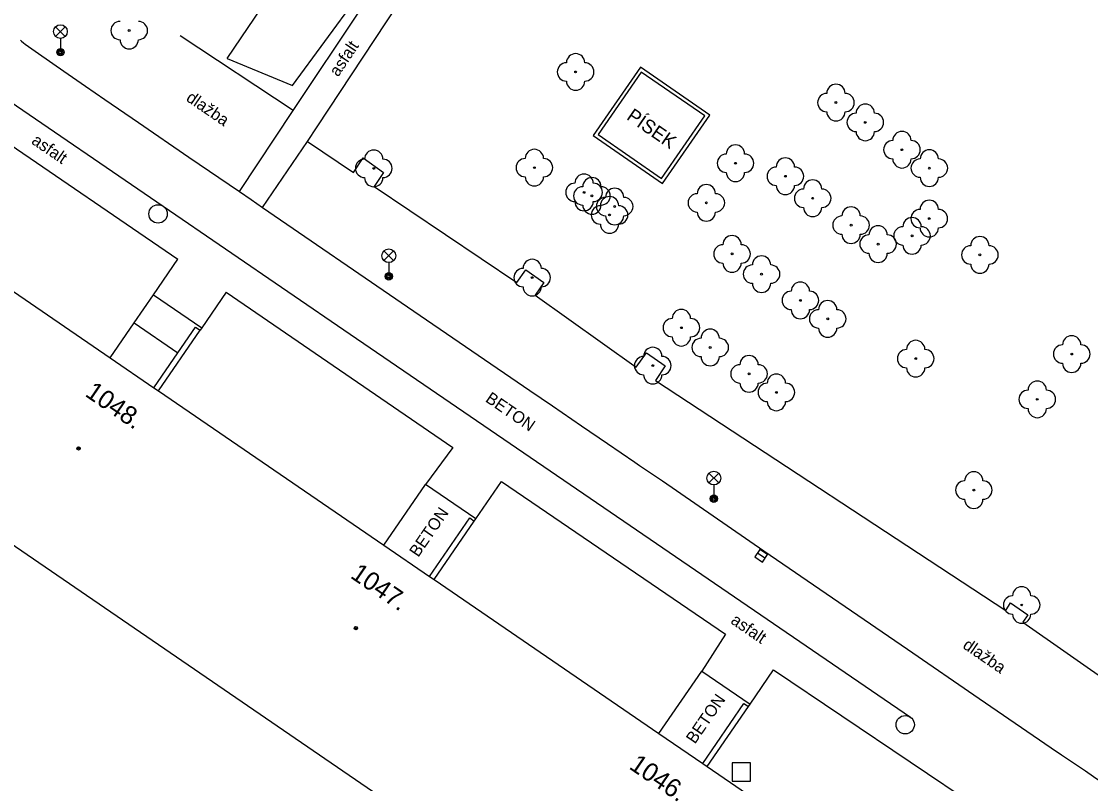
# Model space of a CAD drawing. Extents: x -539515 to -538098, y -1182060 to -1180157.
# Drawn here: x -538687.3 to -538629, y -1181340.3 to -1181298.7 of the extents above; entities that cross this region are included whole.
import ezdxf

# ---------------------------------------------------------------- set-up
doc = ezdxf.new("R2010")
doc.units = 0
for name, color, linetype in [('Vrstva 1', 7, 'Continuous'), ('Vrstva 13', 7, 'Continuous'), ('Vrstva 21', 7, 'Continuous'), ('Vrstva 22', 7, 'Continuous'), ('Vrstva 26', 7, 'Continuous'), ('Vrstva 27', 7, 'Continuous'), ('Vrstva 33', 7, 'Continuous'), ('Vrstva 39', 7, 'Continuous'), ('Vrstva 40', 7, 'Continuous'), ('Vrstva 41', 7, 'Continuous'), ('Vrstva 47', 7, 'Continuous'), ('Vrstva 68', 7, 'Continuous'), ('Vrstva 88', 7, 'Continuous')]:
    doc.layers.add(name, color=color, linetype=linetype)

msp = doc.modelspace()

# ---------------------------------------------------------------- linework, layer by layer
at = {"layer": 'Vrstva 1'}
for p, q in [((-538724.84, -1181301.89), (-538635.14, -1181363.33)), ((-538682.46, -1181317.088), (-538681.15, -1181315.18)), ((-538681.15, -1181315.18), (-538678.77, -1181316.81))]:
    msp.add_line(p, q, dxfattribs=at)
for points in [[(-538694.6, -1181308.773), (-538682.46, -1181317.088)], [(-538682.46, -1181317.088), (-538680.078, -1181318.719)], [(-538680.078, -1181318.719), (-538679.831, -1181318.889)], [(-538679.831, -1181318.889), (-538667.542, -1181327.306)], [(-538667.542, -1181327.306), (-538665.045, -1181329.015)], [(-538665.045, -1181329.015), (-538664.798, -1181329.185)], [(-538664.798, -1181329.185), (-538652.533, -1181337.586)], [(-538652.533, -1181337.586), (-538650.149, -1181339.218)], [(-538650.149, -1181339.218), (-538649.902, -1181339.388)], [(-538649.902, -1181339.388), (-538637.736, -1181347.722)]]:
    msp.add_lwpolyline(points, dxfattribs=at)
at = {"layer": 'Vrstva 13'}
for p, q in [((-538672.49, -1181303.59), (-538678.657, -1181299.511)), ((-538690.92, -1181303.4), (-538678.77, -1181311.7)), ((-538671.707, -1181305.275), (-538669.196, -1181306.972)), ((-538668.06, -1181307.74), (-538660.29, -1181312.97)), ((-538658.81, -1181312.97), (-538659.291, -1181313.663)), ((-538680.104, -1181313.648), (-538677.475, -1181315.449)), ((-538676.14, -1181313.5), (-538663.78, -1181321.97)), ((-538659.291, -1181313.663), (-538653.78, -1181317.59)), ((-538652.73, -1181318.33), (-538633.61, -1181330.87)), ((-538663.78, -1181321.97), (-538665.27, -1181323.99)), ((-538661.13, -1181323.83), (-538648.91, -1181332.17)), ((-538667.542, -1181327.306), (-538665.27, -1181323.99)), ((-538662.527, -1181325.869), (-538665.27, -1181323.99)), ((-538632.69, -1181331.5), (-538606.03, -1181350.16)), ((-538648.91, -1181332.17), (-538650.2, -1181334.18)), ((-538652.533, -1181337.586), (-538650.2, -1181334.18)), ((-538650.2, -1181334.18), (-538647.568, -1181335.981)), ((-538646.28, -1181334.1), (-538634.05, -1181342.34))]:
    msp.add_line(p, q, dxfattribs=at)
for points in [[(-538671.17, -1181304.48), (-538663.02, -1181292.1)], [(-538672.49, -1181303.59), (-538665.1, -1181292.51)], [(-538675.42, -1181308.02), (-538672.49, -1181303.59)], [(-538674.15, -1181308.89), (-538671.707, -1181305.275), (-538671.17, -1181304.48)], [(-538669.196, -1181306.972), (-538668.66, -1181306.18), (-538667.56, -1181306.97), (-538668.06, -1181307.74)], [(-538681.15, -1181315.18), (-538680.104, -1181313.648), (-538678.77, -1181311.7)], [(-538660.29, -1181312.97), (-538659.79, -1181312.29), (-538658.81, -1181312.97)], [(-538676.14, -1181313.5), (-538677.475, -1181315.449), (-538677.56, -1181315.573)], [(-538653.78, -1181317.59), (-538653.21, -1181316.81), (-538652.19, -1181317.53), (-538652.73, -1181318.33)], [(-538662.611, -1181325.992), (-538662.527, -1181325.869), (-538661.13, -1181323.83)], [(-538633.61, -1181330.87), (-538633.36, -1181330.45), (-538632.41, -1181331.11), (-538632.69, -1181331.5)], [(-538647.653, -1181336.105), (-538647.568, -1181335.981), (-538646.28, -1181334.1)]]:
    msp.add_lwpolyline(points, dxfattribs=at)
at = {"layer": 'Vrstva 21'}
for p, q in [((-538676.09, -1181300.75), (-538670.086, -1181291.901)), ((-538672.53, -1181302.22), (-538666.46, -1181293.99)), ((-538676.09, -1181300.75), (-538672.53, -1181302.22))]:
    msp.add_line(p, q, dxfattribs=at)
at = {"layer": 'Vrstva 22'}
for centre in [(-538681.43, -1181299.23), (-538657.08, -1181301.49), (-538642.88, -1181303.16), (-538641.28, -1181304.24), (-538639.28, -1181305.73), (-538668.09, -1181306.75), (-538659.33, -1181306.71), (-538648.36, -1181306.47), (-538637.787, -1181306.736), (-538645.64, -1181307.18), (-538656.62, -1181308.06), (-538656.19, -1181308.25), (-538649.95, -1181308.63), (-538644.15, -1181308.38), (-538655.23, -1181309.29), (-538654.95, -1181308.83), (-538642.055, -1181309.847), (-538637.79, -1181309.49), (-538638.73, -1181310.43), (-538640.58, -1181310.88), (-538648.548, -1181311.416), (-538635.03, -1181311.47), (-538659.45, -1181312.71), (-538646.94, -1181312.52), (-538644.822, -1181313.952), (-538643.33, -1181314.96), (-538651.311, -1181315.441), (-538649.74, -1181316.52), (-538630.02, -1181316.88), (-538638.53, -1181317.13), (-538652.87, -1181317.51), (-538647.62, -1181317.959), (-538646.13, -1181318.97), (-538631.9, -1181319.35), (-538635.36, -1181324.3), (-538632.75, -1181330.57)]:
    msp.add_circle(centre, 0.05, dxfattribs=at)
for centre, start, end in [((-538681.93, -1181299.23), 90, 270), ((-538680.93, -1181299.23), 270, 90), ((-538681.43, -1181299.73), 180, 0), ((-538657.08, -1181300.99), 0, 180), ((-538657.58, -1181301.49), 90, 270), ((-538656.58, -1181301.49), 270, 90), ((-538657.08, -1181301.99), 180, 0), ((-538642.88, -1181302.66), 0, 180), ((-538643.38, -1181303.16), 90, 270), ((-538642.38, -1181303.16), 270, 90), ((-538641.28, -1181303.74), 0, 180), ((-538642.88, -1181303.66), 180, 0), ((-538641.78, -1181304.24), 90, 270), ((-538640.78, -1181304.24), 270, 90), ((-538641.28, -1181304.74), 180, 0), ((-538639.28, -1181305.23), 0, 180), ((-538668.09, -1181306.25), 0, 180), ((-538659.33, -1181306.21), 0, 180), ((-538648.36, -1181305.97), 0, 180), ((-538639.78, -1181305.73), 90, 270), ((-538638.78, -1181305.73), 270, 90), ((-538637.787, -1181306.236), 0, 180), ((-538668.59, -1181306.75), 90, 270), ((-538667.59, -1181306.75), 270, 90), ((-538659.83, -1181306.71), 90, 270), ((-538658.83, -1181306.71), 270, 90), ((-538648.86, -1181306.47), 90, 270), ((-538647.86, -1181306.47), 270, 90), ((-538645.64, -1181306.68), 0, 180), ((-538639.28, -1181306.23), 180, 0), ((-538638.287, -1181306.736), 90, 270), ((-538637.287, -1181306.736), 270, 90), ((-538646.14, -1181307.18), 90, 270), ((-538645.14, -1181307.18), 270, 90), ((-538668.09, -1181307.25), 180, 0), ((-538659.33, -1181307.21), 180, 0), ((-538656.62, -1181307.56), 0, 180), ((-538656.19, -1181307.75), 0, 180), ((-538648.36, -1181306.97), 180, 0), ((-538644.15, -1181307.88), 0, 180), ((-538637.787, -1181307.236), 180, 0), ((-538657.12, -1181308.06), 90, 270), ((-538656.69, -1181308.25), 90, 270), ((-538656.12, -1181308.06), 270, 90), ((-538655.69, -1181308.25), 270, 90), ((-538654.95, -1181308.33), 0, 180), ((-538649.95, -1181308.13), 0, 180), ((-538645.64, -1181307.68), 180, 0), ((-538644.65, -1181308.38), 90, 270), ((-538643.65, -1181308.38), 270, 90), ((-538656.62, -1181308.56), 180, 0), ((-538655.45, -1181308.83), 90, 270), ((-538655.23, -1181308.79), 0, 180), ((-538654.45, -1181308.83), 270, 90), ((-538650.45, -1181308.63), 90, 270), ((-538649.45, -1181308.63), 270, 90), ((-538637.79, -1181308.99), 0, 180), ((-538656.19, -1181308.75), 180, 0), ((-538655.73, -1181309.29), 90, 270), ((-538654.73, -1181309.29), 270, 90), ((-538649.95, -1181309.13), 180, 0), ((-538644.15, -1181308.88), 180, 0), ((-538642.055, -1181309.347), 0, 180), ((-538638.29, -1181309.49), 90, 270), ((-538637.29, -1181309.49), 270, 90), ((-538655.23, -1181309.79), 180, 0), ((-538654.95, -1181309.33), 180, 0), ((-538642.555, -1181309.847), 90, 270), ((-538641.555, -1181309.847), 270, 90), ((-538638.73, -1181309.93), 0, 180), ((-538648.548, -1181310.916), 0, 180), ((-538642.055, -1181310.347), 180, 0), ((-538641.08, -1181310.88), 90, 270), ((-538640.58, -1181310.38), 0, 180), ((-538640.08, -1181310.88), 270, 90), ((-538639.23, -1181310.43), 90, 270), ((-538637.79, -1181309.99), 180, 0), ((-538638.23, -1181310.43), 270, 90), ((-538649.048, -1181311.416), 90, 270), ((-538648.048, -1181311.416), 270, 90), ((-538638.73, -1181310.93), 180, 0), ((-538635.53, -1181311.47), 90, 270), ((-538635.03, -1181310.97), 0, 180), ((-538634.53, -1181311.47), 270, 90), ((-538646.94, -1181312.02), 0, 180), ((-538640.58, -1181311.38), 180, 0), ((-538659.45, -1181312.21), 0, 180), ((-538648.548, -1181311.916), 180, 0), ((-538647.44, -1181312.52), 90, 270), ((-538646.44, -1181312.52), 270, 90), ((-538635.03, -1181311.97), 180, 0), ((-538659.95, -1181312.71), 90, 270), ((-538658.95, -1181312.71), 270, 90), ((-538659.45, -1181313.21), 180, 0), ((-538646.94, -1181313.02), 180, 0), ((-538644.822, -1181313.452), 0, 180), ((-538645.322, -1181313.952), 90, 270), ((-538644.322, -1181313.952), 270, 90), ((-538651.311, -1181314.941), 0, 180), ((-538644.822, -1181314.452), 180, 0), ((-538643.83, -1181314.96), 90, 270), ((-538643.33, -1181314.46), 0, 180), ((-538642.83, -1181314.96), 270, 90), ((-538651.811, -1181315.441), 90, 270), ((-538650.811, -1181315.441), 270, 90), ((-538649.74, -1181316.02), 0, 180), ((-538643.33, -1181315.46), 180, 0), ((-538651.311, -1181315.941), 180, 0), ((-538650.24, -1181316.52), 90, 270), ((-538649.24, -1181316.52), 270, 90), ((-538638.53, -1181316.63), 0, 180), ((-538630.02, -1181316.38), 0, 180), ((-538652.87, -1181317.01), 0, 180), ((-538639.03, -1181317.13), 90, 270), ((-538638.03, -1181317.13), 270, 90), ((-538630.52, -1181316.88), 90, 270), ((-538629.52, -1181316.88), 270, 90), ((-538653.37, -1181317.51), 90, 270), ((-538652.37, -1181317.51), 270, 90), ((-538649.74, -1181317.02), 180, 0), ((-538647.62, -1181317.459), 0, 180), ((-538630.02, -1181317.38), 180, 0), ((-538648.12, -1181317.959), 90, 270), ((-538647.12, -1181317.959), 270, 90), ((-538646.13, -1181318.47), 0, 180), ((-538638.53, -1181317.63), 180, 0), ((-538652.87, -1181318.01), 180, 0), ((-538647.62, -1181318.459), 180, 0), ((-538646.63, -1181318.97), 90, 270), ((-538645.63, -1181318.97), 270, 90), ((-538631.9, -1181318.85), 0, 180), ((-538632.4, -1181319.35), 90, 270), ((-538631.4, -1181319.35), 270, 90), ((-538646.13, -1181319.47), 180, 0), ((-538631.9, -1181319.85), 180, 0), ((-538635.86, -1181324.3), 90, 270), ((-538635.36, -1181323.8), 0, 180), ((-538634.86, -1181324.3), 270, 90), ((-538635.36, -1181324.8), 180, 0), ((-538632.75, -1181330.07), 0, 180), ((-538633.25, -1181330.57), 90, 270), ((-538632.25, -1181330.57), 270, 90), ((-538632.75, -1181331.07), 180, 0)]:
    msp.add_arc(centre, 0.5, start, end, dxfattribs=at)
at = {"layer": 'Vrstva 26'}
msp.add_lwpolyline([(-538648.54, -1181340.19), (-538647.54, -1181340.19), (-538647.54, -1181339.19), (-538648.54, -1181339.19)], close=True, dxfattribs=at)
at = {"layer": 'Vrstva 27'}
msp.add_line((-538646.753, -1181328.024), (-538647.165, -1181327.742), dxfattribs=at)
msp.add_lwpolyline([(-538646.611, -1181327.818), (-538647.024, -1181327.535), (-538647.307, -1181327.948), (-538646.894, -1181328.231)], close=True, dxfattribs=at)
for centre in [(-538679.853, -1181309.233), (-538639.103, -1181337.103)]:
    msp.add_circle(centre, 0.5, dxfattribs=at)
at = {"layer": 'Vrstva 33'}
for p, q in [((-538685.445, -1181299.55), (-538684.915, -1181299.02)), ((-538685.445, -1181299.02), (-538684.915, -1181299.55)), ((-538685.18, -1181299.66), (-538685.18, -1181300.41)), ((-538667.535, -1181311.78), (-538667.005, -1181311.25)), ((-538667.535, -1181311.25), (-538667.005, -1181311.78)), ((-538667.27, -1181311.89), (-538667.27, -1181312.64)), ((-538649.805, -1181323.91), (-538649.275, -1181323.38)), ((-538649.805, -1181323.38), (-538649.275, -1181323.91)), ((-538649.54, -1181324.02), (-538649.54, -1181324.77))]:
    msp.add_line(p, q, dxfattribs=at)
for centre, radius in [((-538685.18, -1181299.285), 0.375), ((-538685.18, -1181300.41), 0.2), ((-538685.18, -1181300.41), 0.145), ((-538685.18, -1181300.41), 0.0876), ((-538667.27, -1181311.515), 0.375), ((-538667.27, -1181312.64), 0.2), ((-538667.27, -1181312.64), 0.145), ((-538667.27, -1181312.64), 0.0876), ((-538649.54, -1181323.645), 0.375), ((-538649.54, -1181324.77), 0.2), ((-538649.54, -1181324.77), 0.145), ((-538649.54, -1181324.77), 0.0876)]:
    msp.add_circle(centre, radius, dxfattribs=at)
at = {"layer": 'Vrstva 39'}
for centre, radius in [((-538684.195, -1181322.024), 0.09), ((-538684.195, -1181322.024), 0.0398), ((-538669.062, -1181331.834), 0.09), ((-538669.062, -1181331.834), 0.0398)]:
    msp.add_circle(centre, radius, dxfattribs=at)
at = {"layer": 'Vrstva 68'}
for p, q in [((-538679.831, -1181318.889), (-538677.56, -1181315.573)), ((-538664.798, -1181329.185), (-538662.611, -1181325.992)), ((-538649.902, -1181339.388), (-538647.653, -1181336.105))]:
    msp.add_line(p, q, dxfattribs=at)
for points in [[(-538680.078, -1181318.719), (-538678.77, -1181316.81), (-538677.807, -1181315.404), (-538677.56, -1181315.573)], [(-538665.045, -1181329.015), (-538662.858, -1181325.823), (-538662.611, -1181325.992)], [(-538650.149, -1181339.218), (-538647.901, -1181335.935), (-538647.653, -1181336.105)]]:
    msp.add_lwpolyline(points, dxfattribs=at)
at = {"layer": 'Vrstva 88'}
for p, q in [((-538696.576, -1181297.176), (-538679.57, -1181308.82)), ((-538653.55, -1181301.22), (-538656.129, -1181304.952)), ((-538653.499, -1181301.498), (-538655.851, -1181304.901)), ((-538649.76, -1181303.84), (-538653.55, -1181301.22)), ((-538650.037, -1181303.89), (-538653.499, -1181301.498)), ((-538652.389, -1181307.293), (-538650.037, -1181303.89)), ((-538652.338, -1181307.571), (-538649.76, -1181303.84)), ((-538656.129, -1181304.952), (-538652.338, -1181307.571)), ((-538655.851, -1181304.901), (-538652.389, -1181307.293)), ((-538679.57, -1181308.82), (-538669.384, -1181315.789)), ((-538674.15, -1181308.89), (-538666.245, -1181314.3)), ((-538669.384, -1181315.789), (-538654.102, -1181326.24)), ((-538654.102, -1181326.24), (-538638.82, -1181336.69)), ((-538646.81, -1181327.61), (-538638.982, -1181332.988))]:
    msp.add_line(p, q, dxfattribs=at)
for points in [[(-538687.358, -1181299.762), (-538687.297, -1181299.817), (-538687.2, -1181299.895), (-538687.1, -1181299.97), (-538686.371, -1181300.484), (-538685.004, -1181301.44), (-538683.808, -1181302.271), (-538682.761, -1181302.995)], [(-538682.761, -1181302.995), (-538680.927, -1181304.255), (-538678.175, -1181306.137), (-538675.42, -1181308.02), (-538674.785, -1181308.455)], [(-538674.785, -1181308.455), (-538674.15, -1181308.89)], [(-538666.245, -1181314.3), (-538659.578, -1181318.863)], [(-538659.578, -1181318.863), (-538658.34, -1181319.71)], [(-538658.34, -1181319.71), (-538656.752, -1181320.795), (-538655.345, -1181321.754), (-538653.847, -1181322.776), (-538653.589, -1181322.954), (-538652.35, -1181323.8)], [(-538652.35, -1181323.8), (-538649.579, -1181325.704), (-538646.81, -1181327.61)], [(-538638.982, -1181332.988), (-538635.067, -1181335.675), (-538631.15, -1181338.36)], [(-538631.15, -1181338.36), (-538630.571, -1181338.752), (-538629.7, -1181339.334), (-538629.264, -1181339.626), (-538628.83, -1181339.92), (-538624.923, -1181342.589)]]:
    msp.add_lwpolyline(points, dxfattribs=at)

# ---------------------------------------------------------------- texts
at = {"layer": 'Vrstva 40'}
for s, rotation, p in [('asfalt', 56.23685, (-538670.034, -1181301.793)), ('dlažba', 325.6045, (-538678.373, -1181303.027)), ('asfalt', 325.66194, (-538686.809, -1181305.365)), ('BETON', 325.63485, (-538662.046, -1181319.44)), ('BETON', 55.59526, (-538665.665, -1181328.001)), ('asfalt', 325.63535, (-538648.672, -1181331.535)), ('dlažba', 325.6045, (-538636.014, -1181332.889)), ('BETON', 55.59526, (-538650.571, -1181338.189))]:
    msp.add_text(s, height=0.65, rotation=rotation, dxfattribs=at).set_placement(p)
at = {"layer": 'Vrstva 41'}
msp.add_text('PÍSEK', height=0.75, rotation=325.35824, dxfattribs=at).set_placement((-538654.352, -1181304.042))
at = {"layer": 'Vrstva 47'}
for s, p in [('1048.', (-538683.888, -1181319.14)), ('1047.', (-538669.42, -1181329.05)), ('1046.', (-538654.214, -1181339.466))]:
    msp.add_text(s, height=1, rotation=325.59081, dxfattribs=at).set_placement(p)

doc.saveas('drawing.dxf')
